(* Logix 5000 project; controller HARDY_HI6800_AWC_Sample_V30_V2_1 vendor 1 type 14 code 196 rev 30.17; software revision 30.00 *)

TASK MainTask (continuous, watchdog 500 ms) : MainProgram, HARDY_HI6800_Scale_0

MODULES
   Local : vendor 1 type 14 code 196 (5069 0, rev 30.17)
      HI6800 : vendor 258 type 43 code 12 (Ethernet 192.168.1.3, rev 2.92, StandardDataDriven RPI 10 ms)
END_MODULES

PROGRAM HARDY_HI6800_Scale_0   (* main routine MainRoutine *)
// Developed within the V2_2 sample program.
VAR
   C2_Cal_Scale : BOOL;
   C2_Scale_ONS1 : BOOL;
   C2_Search : BOOL;
   C2_Search_ONS1 : BOOL;
   C2UnlatchONS1 : BOOL;
   Command_Reset_TON1 : TIMER := (PRE := 2000);
   Gross_Weight_Display : REAL := 6800.0;
   Gross_Weight_Display_1DecPt : REAL := 6800.0;
   Gross_Wt_x10_DINT : DINT := 68000;
   HI6800_Heartbeat_Display : INT := -12928;
   Last_Command_Sent : INT := 16#0066;
   Last_Command_Status_Hex : INT := 16#2c00;
   Net_Weight_Display : REAL := 6800.0;
   Set_Default_Params : BOOL;
   SetDefault_ONS1 : BOOL;
   Tare_Scale : BOOL;
   Tare_Scale_ONS1 : BOOL;
   TradCalHigh_ONS1 : BOOL;
   TradCalLow_ONS1 : BOOL;
   Traditional_Cal_High : BOOL;
   Traditional_Cal_Low : BOOL;
   Zero_Scale : BOOL;
   Zero_Scale_ONS1 : BOOL;
END_VAR

ROUTINE MainRoutine   (* ladder *)
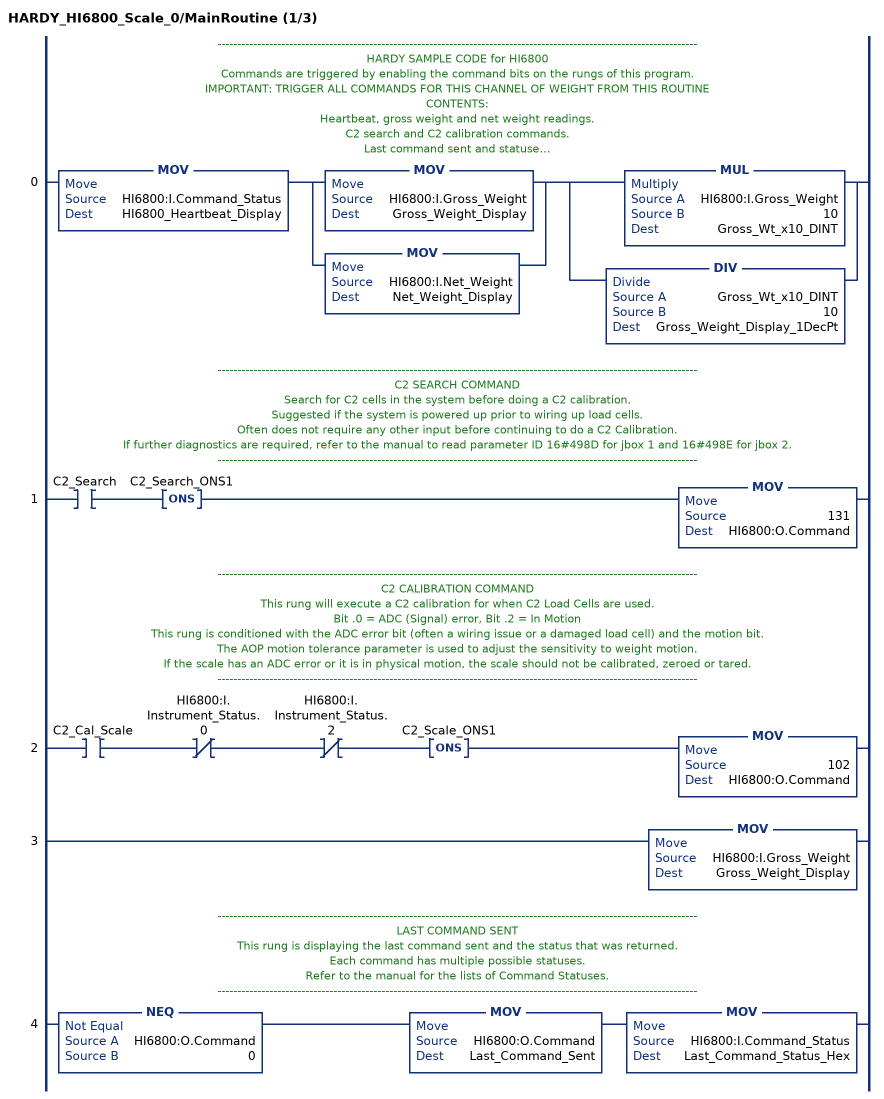
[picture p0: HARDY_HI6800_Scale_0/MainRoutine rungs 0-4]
   // ------------------------------------------------------------------------------------------------------------------------
   // HARDY SAMPLE CODE for HI6800
   // Commands are triggered by enabling the command bits on the rungs of this program.
   // IMPORTANT: TRIGGER ALL COMMANDS FOR THIS CHANNEL OF WEIGHT FROM THIS ROUTINE
   // CONTENTS:
   // Heartbeat, gross weight and net weight readings.
   // C2 search and C2 calibration commands.
   // Last command sent and statuses
   // Zero, Tare and other commands.
   // It is recommended to configure the parameters via the AOP prior to sending commands.
   // This is a display rung for the channel heartbeat, weight readings and an example of reducing the displayed number of decimal points.
   // ------------------------------------------------------------------------------------------------------------------------
   0: MOV(HI6800:I.Command_Status,HI6800_Heartbeat_Display)[MOV(HI6800:I.Gross_Weight,Gross_Weight_Display) ,MOV(HI6800:I.Net_Weight,Net_Weight_Display) ][MUL(HI6800:I.Gross_Weight,10,Gross_Wt_x10_DINT) ,DIV(Gross_Wt_x10_DINT,10,Gross_Weight_Display_1DecPt) ];
   // ------------------------------------------------------------------------------------------------------------------------
   // C2 SEARCH COMMAND
   // Search for C2 cells in the system before doing a C2 calibration.
   // Suggested if the system is powered up prior to wiring up load cells.
   // Often does not require any other input before continuing to do a C2 Calibration.
   // If further diagnostics are required, refer to the manual to read parameter ID 16#498D for jbox 1 and 16#498E for jbox 2.
   // ------------------------------------------------------------------------------------------------------------------------
   1: XIC(C2_Search)ONS(C2_Search_ONS1)MOV(131,HI6800:O.Command);
   // ------------------------------------------------------------------------------------------------------------------------
   // C2 CALIBRATION COMMAND
   // This rung will execute a C2 calibration for when C2 Load Cells are used.
   // Bit .0 = ADC (Signal) error, Bit .2 = In Motion
   // This rung is conditioned with the ADC error bit (often a wiring issue or a damaged load cell) and the motion bit.
   // The AOP motion tolerance parameter is used to adjust the sensitivity to weight motion.
   // If the scale has an ADC error or it is in physical motion, the scale should not be calibrated, zeroed or tared.
   // ------------------------------------------------------------------------------------------------------------------------
   2: XIC(C2_Cal_Scale)XIO(HI6800:I.Instrument_Status.0)XIO(HI6800:I.Instrument_Status.2)ONS(C2_Scale_ONS1)MOV(102,HI6800:O.Command);
   3: MOV(HI6800:I.Gross_Weight,Gross_Weight_Display);
   // ------------------------------------------------------------------------------------------------------------------------
   // LAST COMMAND SENT
   // This rung is displaying the last command sent and the status that was returned.
   // Each command has multiple possible statuses.
   // Refer to the manual for the lists of Command Statuses.
   // ------------------------------------------------------------------------------------------------------------------------
   4: NEQ(HI6800:O.Command,0)MOV(HI6800:O.Command,Last_Command_Sent)MOV(HI6800:I.Command_Status,Last_Command_Status_Hex);
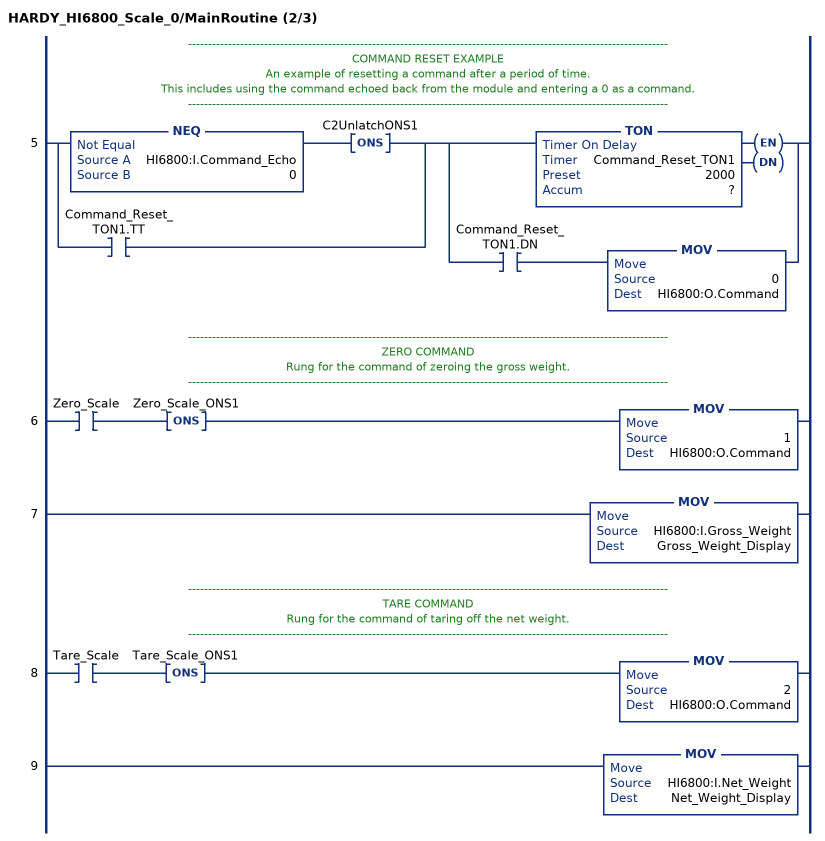
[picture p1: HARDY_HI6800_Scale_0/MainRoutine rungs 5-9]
   // ------------------------------------------------------------------------------------------------------------------------
   // COMMAND RESET EXAMPLE
   // An example of resetting a command after a period of time.
   // This includes using the command echoed back from the module and entering a 0 as a command.
   // ------------------------------------------------------------------------------------------------------------------------
   5: [NEQ(HI6800:I.Command_Echo,0) ONS(C2UnlatchONS1) ,XIC(Command_Reset_TON1.TT) ][TON(Command_Reset_TON1,?,?) ,XIC(Command_Reset_TON1.DN) MOV(0,HI6800:O.Command) ];
   // ------------------------------------------------------------------------------------------------------------------------
   // ZERO COMMAND
   // Rung for the command of zeroing the gross weight.
   // ------------------------------------------------------------------------------------------------------------------------
   6: XIC(Zero_Scale)ONS(Zero_Scale_ONS1)MOV(1,HI6800:O.Command);
   7: MOV(HI6800:I.Gross_Weight,Gross_Weight_Display);
   // ------------------------------------------------------------------------------------------------------------------------
   // TARE COMMAND
   // Rung for the command of taring off the net weight.
   // ------------------------------------------------------------------------------------------------------------------------
   8: XIC(Tare_Scale)ONS(Tare_Scale_ONS1)MOV(2,HI6800:O.Command);
   9: MOV(HI6800:I.Net_Weight,Net_Weight_Display);
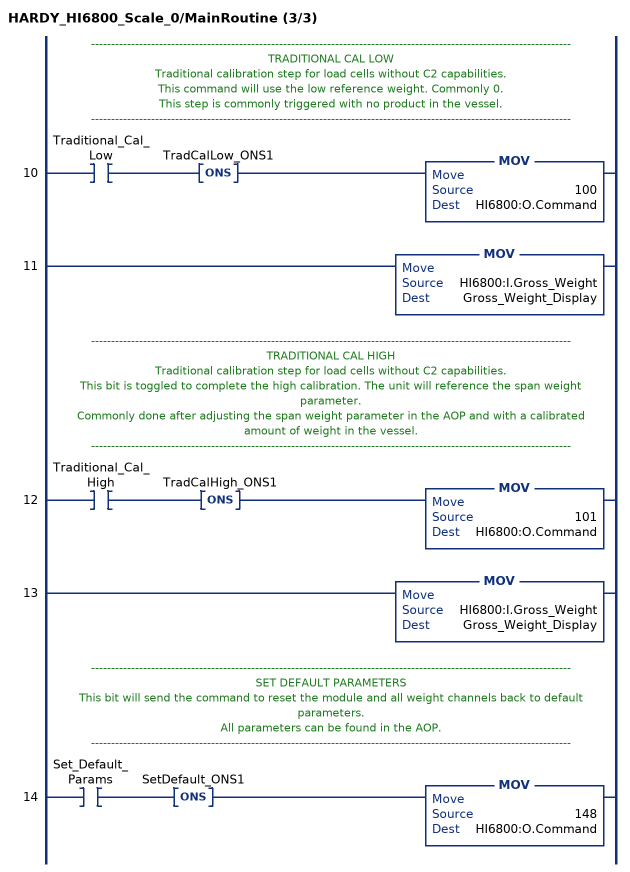
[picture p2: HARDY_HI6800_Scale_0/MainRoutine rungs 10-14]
   // ------------------------------------------------------------------------------------------------------------------------
   // TRADITIONAL CAL LOW
   // Traditional calibration step for load cells without C2 capabilities.
   // This command will use the low reference weight. Commonly 0.
   // This step is commonly triggered with no product in the vessel.
   // ------------------------------------------------------------------------------------------------------------------------
   10: XIC(Traditional_Cal_Low)ONS(TradCalLow_ONS1)MOV(100,HI6800:O.Command);
   11: MOV(HI6800:I.Gross_Weight,Gross_Weight_Display);
   // ------------------------------------------------------------------------------------------------------------------------
   // TRADITIONAL CAL HIGH
   // Traditional calibration step for load cells without C2 capabilities.
   // This bit is toggled to complete the high calibration. The unit will reference the span weight parameter.
   // Commonly done after adjusting the span weight parameter in the AOP and with a calibrated amount of weight in the vessel.
   // ------------------------------------------------------------------------------------------------------------------------
   12: XIC(Traditional_Cal_High)ONS(TradCalHigh_ONS1)MOV(101,HI6800:O.Command);
   13: MOV(HI6800:I.Gross_Weight,Gross_Weight_Display);
   // ------------------------------------------------------------------------------------------------------------------------
   // SET DEFAULT PARAMETERS
   // This bit will send the command to reset the module and all weight channels back to default parameters.
   // All parameters can be found in the AOP.
   // ------------------------------------------------------------------------------------------------------------------------
   14: XIC(Set_Default_Params)ONS(SetDefault_ONS1)MOV(148,HI6800:O.Command);
END_ROUTINE
END_PROGRAM

PROGRAM MainProgram   (* main routine MainRoutine *)

ROUTINE MainRoutine   (* ladder *)
END_ROUTINE
END_PROGRAM
